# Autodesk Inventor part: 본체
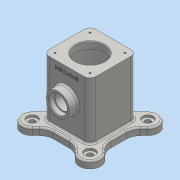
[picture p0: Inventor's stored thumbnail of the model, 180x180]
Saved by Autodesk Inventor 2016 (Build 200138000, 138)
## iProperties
Created: 2019-11
Part Number: 본체
Material: 일반
Document SubType Name: Modeling
Designer: user
Density: 1 g/cm^3
Appearance: 기본값
Mass: 398.611 g
Surface Area: 879.476 cm^2
Volume: 398.611 cm^3
Author: user
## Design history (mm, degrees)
sketch "스케치1"
  geometry: L1 (-49, -49)-(49, -49); L2 (49, -49)-(49, 49); L3 (49, 49)-(-49, 49); L4 (-49, 49)-(-49, -49); L5 (-49, -49)-(49, 49); L6 (49, -49)-(-49, 49); L7 (-49.497, -49.497)-(49.497, 49.497); L8 (-36.77, -62.225)-(62.225, 36.77); L9 (36.77, 62.225)-(-62.225, -36.77); L10 (49.497, -49.497)-(-49.497, 49.497); L11 (62.225, -36.77)-(-36.77, 62.225); L12 (-62.225, 36.77)-(36.77, -62.225); A1 r 18 centre (-49.497, -49.497) between (-62.225, -36.77) and (-36.77, -62.225); A2 r 18 centre (49.497, 49.497) between (62.225, 36.77) and (36.77, 62.225); A3 r 18 centre (49.497, -49.497) between (36.77, -62.225) and (62.225, -36.77); A4 r 18 centre (-49.497, 49.497) between (-36.77, 62.225) and (-62.225, 36.77); A5 r 70 centre (0, 0) between (-49.497, 49.497) and (49.497, 49.497); 1 further point
  constraints: 28 end point, 10 point on circle, 8 tangent, 5 centre point, 4 midpoint, 4 parallel, 2 point on line, 1 coincident, 1 horizontal, 1 perpendicular
  dimensions: "d0" = 98 distance of L3.end L2.end; "d1" = 98 distance of L2.end L1.end; "d2" = 18 radius of A4; "d3" = 18 radius of A2; "d4" = 140 diameter of A5
extrude "돌출1" new body sketch "스케치1" distance "d5" = 12; taper "d6" = 0 deg
sketch "스케치2"
  geometry: L1 (-40, -40)-(40, -40); L2 (40, -40)-(40, 40); L3 (40, 40)-(-40, 40); L4 (-40, 40)-(-40, -40); L5 (-40, -40)-(40, 40); L6 (40, -40)-(-40, 40); 1 further point
  constraints: 12 end point, 2 midpoint, 2 parallel, 1 horizontal, 1 perpendicular
  dimensions: "d7" = 80 distance of L3.end L2.end; "d8" = 80 distance of L2.end L1.end
extrude "돌출2" join sketch "스케치2" distance "d9" = 98; taper "d10" = 0 deg
node "작업 평면1"
sketch "스케치4"
  geometry: C1 r 20 at (0, 61); 1 further point
  constraints: 1 centre point, 1 vertical alignment
  dimensions: "d14" = 40 diameter of C1; "d15" = 61 distance of point (0, 0) C1.centre
extrude "돌출3" join sketch "스케치4" stored distance "d16" = 98; taper "d17" = 0 deg
sketch "스케치5"
  geometry: C1 r 25 at (0, 0); 1 further point
  constraints: 1 centre point, 1 coincident
  dimensions: "d18" = 50 diameter of C1
extrude "돌출4" cut sketch "스케치5" distance "d19" = 12; taper "d20" = 0 deg
node "작업 평면2"
sketch "스케치6"
  geometry: C1 r 35 at (0, 0); 1 further point
  constraints: 1 centre point, 1 coincident
  dimensions: "d22" = 70 diameter of C1
extrude "돌출5" cut sketch "스케치6" distance "d23" = 86; taper "d24" = 0 deg
sketch "스케치7"
  geometry: C1 r 20 at (0, 0) reference; 2 further points
  constraints: 1 coincident
hole "구멍1" sketch "스케치7" at (0, 0) diameter "d25" = 25; stored, may be unused: countersink angle "d29" = 90 deg, drill point angle "d31" = 118 deg; dims "d26" = 6, "d27" = 30, "d28" = 8, "d30" = 46
sketch "스케치8"
  geometry: L1 (-30, -30)-(30, -30); L2 (30, -30)-(30, 30); L3 (30, 30)-(-30, 30); L4 (-30, 30)-(-30, -30); L5 (-30, -30)-(30, 30); L6 (30, -30)-(-30, 30); 2 further points
  constraints: 12 end point, 2 midpoint, 2 parallel, 1 coincident, 1 horizontal, 1 perpendicular
  dimensions: "d32" = 60 distance of L3.end L2.end; "d33" = 60 distance of L2.end L1.end
hole "구멍2" sketch "스케치8" at (30, 30) diameter "d34" = 3.242; stored, may be unused: countersink angle "d38" = 90 deg, drill point angle "d40" = 118 deg; dims "d35" = 8, "d36" = 30, "d37" = 8, "d39" = 10
node "작업 평면3"
sketch "스케치9"
  geometry: L1 (0, 0)-(-49.497, 49.497); L2 (49, -23.544)-(49, 23.544) reference; 1 further point
  constraints: 2 end point, 1 coincident
  dimensions: "d48" = 70 distance of L1.start L1.end; "d49" = 45 deg angle of L2 L1
hole "구멍3" sketch "스케치9" at (-49.497, 49.497) diameter "d50" = 10; stored, may be unused: countersink angle "d54" = 90 deg, drill point angle "d56" = 118 deg; dims "d51" = 8, "d52" = 18, "d53" = 4, "d55" = 10
fillet "모깎기1" dims "d60" = 10
fillet "모깎기2" dims "d61" = 3
fillet "모깎기3" dims "d62" = 25
fillet "모깎기4" dims "d63" = 3
chamfer "모따기1" distance "d64" = 1; stored, may be unused: second distance "d65" = 2, angle "d66" = 45 deg
fillet "모깎기5" dims "d67" = 3
fillet "모깎기6" dims "d68" = 3
sketch "스케치10"
  geometry: L1 (0, 0)-(60, 0) reference; L2 (16.811, -110)-(43.189, -110) reference; 3 further points
  constraints: 1 midpoint, 1 vertical alignment, 1 other
  dimensions: "d69" = 10 distance from line of L1 point (30, -10)
feature "엠보싱1" sketch "스케치10" dims "d0" = 98, "d1" = 98, "d2" = 18, "d3" = 18, "d4" = 140, "d70" = 0.3, "d71" = 0
node "솔리드1"
mirror "대칭1"
pattern_linear "직사각형 패턴1" dims "d43" = 60
mirror "대칭2"
pattern_circular "원형 패턴1" dims angle "d58" = 360 deg
other parameters: "d13" = -55, "d21" = 55, "d47" = 55
